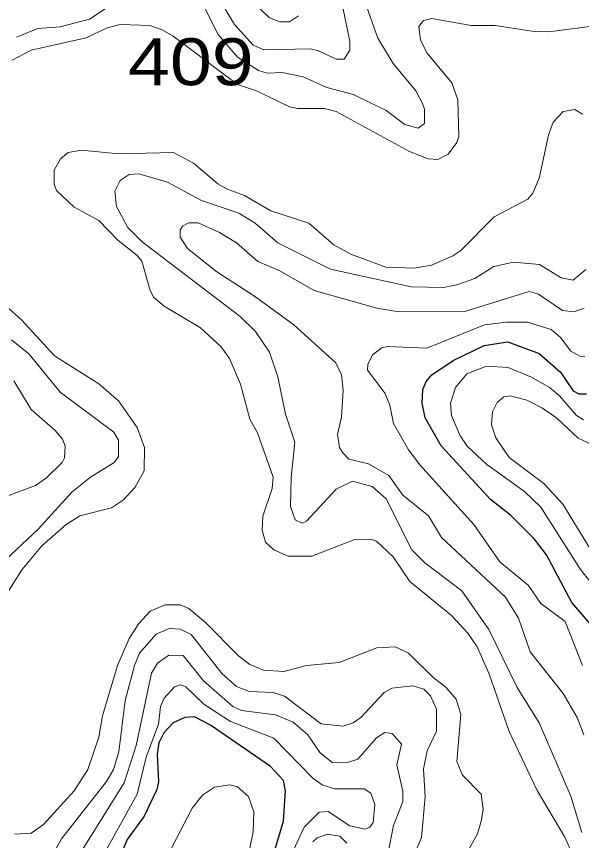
# Model space of a CAD drawing. Extents: x 577 to 602.9, y 7483.8 to 7511.6.
# Drawn here: x 593.033 to 593.996, y 7486.38 to 7487.785 of the extents above; entities that cross this region are included whole.
import ezdxf
from ezdxf.enums import TextEntityAlignment as Align

# ---------------------------------------------------------------- set-up
doc = ezdxf.new("R2010")
doc.units = 0
doc.header["$LTSCALE"] = 0.032
doc.layers.add('1', color=7, linetype='Continuous', lineweight=25)
doc.layers.add('2', color=7, linetype='Continuous', lineweight=13)
doc.layers.add('61', color=7, linetype='Continuous')

msp = doc.modelspace()

# ---------------------------------------------------------------- linework, layer by layer
at = {"layer": '1'}
for points in [[(594.0639, 7486.6885), (593.9796, 7486.7863), (593.9367, 7486.8674), (593.916, 7486.8945), (593.8755, 7486.935), (593.8413, 7486.9621), (593.757, 7487.0535), (593.73, 7487.1012), (593.7244, 7487.1259), (593.726, 7487.1497), (593.7316, 7487.1632), (593.7411, 7487.1744), (593.7777, 7487.199), (593.8302, 7487.2245), (593.8707, 7487.2308), (593.924, 7487.211), (593.9606, 7487.1792), (593.982, 7487.1473), (593.9916, 7487.1418), (594.0051, 7487.1418)], [(593.4715, 7486.3585), (593.4882, 7486.4134), (593.4914, 7486.4651), (593.4882, 7486.4826), (593.466, 7486.5064), (593.3634, 7486.5772), (593.3364, 7486.5915), (593.3197, 7486.5899), (593.2998, 7486.5812), (593.284, 7486.564), (593.2755, 7486.5469), (593.2727, 7486.5279), (593.2751, 7486.4802), (593.2719, 7486.4675), (593.2505, 7486.4221), (593.2218, 7486.3824), (593.1892, 7486.3045)]]:
    msp.add_lwpolyline(points, dxfattribs=at)
at = {"layer": '2'}
for points in [[(593.5137, 7487.7867), (593.4986, 7487.7763), (593.4819, 7487.7763), (593.4641, 7487.783), (593.3906, 7487.8547)], [(593.2163, 7487.8209), (593.1574, 7487.7811)], [(593.375, 7487.8214), (593.4047, 7487.7716), (593.4365, 7487.7366), (593.4548, 7487.7286), (593.5336, 7487.7302), (593.5479, 7487.727), (593.5781, 7487.7127), (593.5916, 7487.7127), (593.6011, 7487.7278), (593.6011, 7487.7429), (593.5852, 7487.8209)], [(593.6266, 7487.8113), (593.6489, 7487.7485), (593.6751, 7487.7056), (593.7141, 7487.6586), (593.7252, 7487.6372), (593.7284, 7487.6276), (593.7284, 7487.603), (593.718, 7487.595), (593.695, 7487.6014), (593.6632, 7487.6252), (593.6075, 7487.6523), (593.5622, 7487.6642), (593.5216, 7487.6825), (593.4858, 7487.6897), (593.4604, 7487.6889), (593.4453, 7487.6936), (593.4095, 7487.7159), (593.3769, 7487.7549), (593.3536, 7487.8006)], [(594.0234, 7487.77), (593.9407, 7487.7596), (593.9121, 7487.7604), (593.8492, 7487.77), (593.8079, 7487.77), (593.7411, 7487.7819), (593.7268, 7487.7787), (593.7188, 7487.7684), (593.722, 7487.7453), (593.7331, 7487.7231), (593.7753, 7487.6722), (593.7856, 7487.6435), (593.7872, 7487.5807), (593.784, 7487.5704), (593.7689, 7487.5505), (593.7514, 7487.5418), (593.7347, 7487.5425), (593.7029, 7487.5553), (593.5781, 7487.6237), (593.5582, 7487.6284), (593.5121, 7487.6284), (593.4986, 7487.6316), (593.4421, 7487.6586), (593.4095, 7487.6698), (593.2998, 7487.7517), (593.2815, 7487.7628), (593.26, 7487.77), (593.2099, 7487.7716), (593.1877, 7487.766), (593.1519, 7487.7493), (593.058, 7487.7278), (593.0254, 7487.7111)], [(593.1574, 7487.7811), (593.1073, 7487.7676), (593.0692, 7487.7652), (593.0326, 7487.7501)], [(593.396, 7487.2022), (593.3817, 7487.2221), (593.3467, 7487.2547), (593.2847, 7487.2913), (593.2672, 7487.3064), (593.2608, 7487.3183), (593.2465, 7487.3684), (593.2385, 7487.3779), (593.2059, 7487.4042), (593.1733, 7487.4376), (593.1312, 7487.4606), (593.101, 7487.4885), (593.097, 7487.4996), (593.097, 7487.5235), (593.1081, 7487.5425), (593.1209, 7487.5537), (593.1439, 7487.5577), (593.2075, 7487.5513), (593.3006, 7487.5537), (593.3348, 7487.5354), (593.3761, 7487.5004), (593.3912, 7487.4917), (593.4214, 7487.4805), (593.4668, 7487.4543), (593.5312, 7487.4328), (593.5741, 7487.3962), (593.6027, 7487.3803), (593.6624, 7487.3581), (593.7109, 7487.3565), (593.7403, 7487.3612), (593.7769, 7487.3772), (593.7904, 7487.3867), (593.8476, 7487.4439), (593.9049, 7487.4742), (593.9136, 7487.4845), (593.924, 7487.5099), (593.9399, 7487.5831), (593.9478, 7487.6054), (593.9653, 7487.6237), (593.9852, 7487.6268), (593.9979, 7487.6189)], [(593.8866, 7486.6416), (593.8381, 7486.7402), (593.792, 7486.8062), (593.7292, 7486.8539), (593.7069, 7486.8762), (593.6632, 7486.9629), (593.6393, 7486.9843), (593.6059, 7486.9931), (593.5781, 7486.9796), (593.5272, 7486.9247), (593.52, 7486.9215), (593.5081, 7486.9271), (593.5002, 7486.9501), (593.501, 7486.9994), (593.5073, 7487.0599), (593.4914, 7487.1076), (593.4787, 7487.1712), (593.4644, 7487.2133), (593.4405, 7487.2483), (593.4143, 7487.2738), (593.2473, 7487.401), (593.2226, 7487.4257), (593.2036, 7487.4614), (593.2004, 7487.4877), (593.2099, 7487.506), (593.225, 7487.5163), (593.2417, 7487.5171), (593.2902, 7487.5028), (593.3483, 7487.4718), (593.4119, 7487.4503), (593.4397, 7487.4328), (593.4787, 7487.3994), (593.5685, 7487.3549), (593.7061, 7487.3247), (593.761, 7487.3231), (593.784, 7487.3278), (593.8143, 7487.339), (593.8469, 7487.3589), (593.8803, 7487.3668), (593.9248, 7487.3628), (593.9614, 7487.3398), (593.982, 7487.3358), (594.0035, 7487.3541)], [(594.0011, 7487.2881), (593.9836, 7487.2817), (593.9637, 7487.2841), (593.9232, 7487.3119), (593.9073, 7487.3167), (593.7991, 7487.2833), (593.6846, 7487.2817), (593.6473, 7487.2881), (593.5407, 7487.3183), (593.4819, 7487.3517), (593.4445, 7487.3676), (593.4079, 7487.3994), (593.3793, 7487.4169), (593.3427, 7487.4336), (593.3268, 7487.4336), (593.3157, 7487.428), (593.3117, 7487.4209), (593.3117, 7487.409), (593.3244, 7487.3899), (593.3745, 7487.3501), (593.4389, 7487.3088), (593.5057, 7487.2595), (593.5773, 7487.1951), (593.5868, 7487.1744), (593.59, 7487.1481), (593.5868, 7487.102), (593.5805, 7487.0726), (593.5837, 7487.0503), (593.5892, 7487.0416), (593.5996, 7487.0305), (593.633, 7487.0225), (593.6679, 7487.0026), (593.6918, 7486.9692), (593.7355, 7486.9342), (593.7578, 7486.8969), (593.8667, 7486.7951), (593.889, 7486.7593), (593.9089, 7486.702), (593.9653, 7486.6313), (593.9892, 7486.5899), (594.0003, 7486.5605)], [(593, 7487.3048), (593.0413, 7487.2682), (593.0978, 7487.207), (593.1733, 7487.1593), (593.2067, 7487.1299), (593.2385, 7487.0845), (593.2513, 7487.0503), (593.2505, 7487.0106), (593.2354, 7486.9827), (593.2155, 7486.9613), (593.1948, 7486.9478), (593.1407, 7486.9342), (593.1177, 7486.9191), (593.0763, 7486.8826), (593.0421, 7486.842), (592.9904, 7486.7609)], [(594.0019, 7487.2054), (593.9932, 7487.2062), (593.9781, 7487.2149), (593.9606, 7487.238), (593.9447, 7487.2515), (593.9041, 7487.2642), (593.8683, 7487.2642), (593.831, 7487.2595), (593.7323, 7487.2197), (593.6656, 7487.2229), (593.656, 7487.2205), (593.6401, 7487.2086), (593.6322, 7487.1919), (593.6314, 7487.1823), (593.6616, 7487.1426), (593.6695, 7487.1227), (593.6759, 7487.0917), (593.7013, 7487.0464), (593.7204, 7487.0209), (593.8127, 7486.9191), (593.8572, 7486.8555), (593.9057, 7486.815), (593.9272, 7486.7847), (593.9685, 7486.7537), (593.9979, 7486.679)], [(593.0246, 7487.234), (593.0541, 7487.2102), (593.1073, 7487.145), (593.1988, 7487.0766), (593.2067, 7487.0631), (593.2067, 7487.0344), (593.1996, 7487.0249), (593.159, 7487.0002), (593.128, 7486.9748), (593.07, 7486.9112), (593.004, 7486.8499)], [(593.9876, 7486.3418), (593.9677, 7486.3864), (593.9208, 7486.4659), (593.8731, 7486.5661), (593.8381, 7486.6655), (593.8182, 7486.7108), (593.8023, 7486.7339), (593.7745, 7486.7641), (593.7037, 7486.8221), (593.6751, 7486.8643), (593.6473, 7486.8905), (593.6369, 7486.8945), (593.6099, 7486.8937), (593.5367, 7486.8651), (593.4962, 7486.8651), (593.4715, 7486.8762), (593.4572, 7486.8889), (593.4517, 7486.9096), (593.4532, 7486.9334), (593.4691, 7486.9804), (593.4707, 7487.0002), (593.4437, 7487.0758), (593.431, 7487.0988), (593.4151, 7487.1585), (593.396, 7487.2022)], [(594.0695, 7486.749), (593.9948, 7486.8428), (593.9272, 7486.9486), (593.8993, 7486.9756), (593.8349, 7487.0217), (593.8015, 7487.0527), (593.7896, 7487.0702), (593.7745, 7487.1052), (593.7729, 7487.1259), (593.7817, 7487.1529), (593.8007, 7487.176), (593.8341, 7487.1895), (593.8715, 7487.1871), (593.9113, 7487.1704), (593.9415, 7487.1529), (593.959, 7487.1386), (593.9876, 7487.1052), (593.9995, 7487.098)], [(593.0064, 7486.9637), (593.0652, 7486.9859), (593.0843, 7486.9986), (593.1105, 7487.0249), (593.1145, 7487.0328), (593.1161, 7487.0527), (593.1113, 7487.0646), (593.0986, 7487.0798), (593.058, 7487.1155), (593.0286, 7487.164)], [(594.0409, 7486.8293), (593.9645, 7486.9541), (593.9319, 7486.9891), (593.8731, 7487.0336), (593.85, 7487.067), (593.8429, 7487.0893), (593.8445, 7487.1116), (593.8524, 7487.1275), (593.8636, 7487.137), (593.8755, 7487.1386), (593.9033, 7487.1314), (593.9296, 7487.1179), (593.9542, 7487.1004), (593.9908, 7487.0662), (594.0138, 7487.0559)], [(593.0294, 7486.3911), (593.058, 7486.3927), (593.0787, 7486.4078), (593.1312, 7486.4651), (593.1543, 7486.5017), (593.1733, 7486.5565), (593.1797, 7486.5931), (593.2051, 7486.679), (593.225, 7486.7251), (593.2417, 7486.7506), (593.2608, 7486.7712), (593.2863, 7486.7824), (593.3117, 7486.7824), (593.3268, 7486.776), (593.3554, 7486.7521), (593.4119, 7486.6949), (593.431, 7486.6806), (593.454, 7486.671), (593.489, 7486.6686), (593.5272, 7486.679), (593.5829, 7486.6838), (593.6473, 7486.7092), (593.6791, 7486.7108), (593.7013, 7486.6997), (593.7427, 7486.6591), (593.7657, 7486.6416), (593.7824, 7486.6217), (593.7904, 7486.5955), (593.784, 7486.5152), (593.7936, 7486.4921), (593.8254, 7486.4595), (593.8286, 7486.4333), (593.8254, 7486.4134), (593.819, 7486.3919), (593.8031, 7486.3633)], [(593.0898, 7486.3474), (593.1097, 7486.3832), (593.1861, 7486.481), (593.198, 7486.5017), (593.2075, 7486.5319), (593.2179, 7486.6193), (593.2338, 7486.679), (593.2425, 7486.6997), (593.2711, 7486.7323), (593.2934, 7486.7418), (593.3117, 7486.741), (593.3308, 7486.7315), (593.3833, 7486.6647), (593.4079, 7486.6432), (593.4302, 7486.6345), (593.4707, 7486.6329), (593.4898, 7486.6265), (593.5526, 7486.5796), (593.5892, 7486.5756), (593.6067, 7486.5812), (593.6202, 7486.5899), (593.66, 7486.6329), (593.6727, 7486.64), (593.7085, 7486.644), (593.7276, 7486.6384), (593.7387, 7486.6273), (593.749, 7486.6042), (593.749, 7486.5669), (593.7331, 7486.5335), (593.7268, 7486.5025), (593.73, 7486.4547), (593.7236, 7486.3856), (593.6918, 7486.31)], [(593.6663, 7486.3569), (593.6759, 7486.4062), (593.6918, 7486.4468), (593.6918, 7486.4643), (593.6815, 7486.5096), (593.6894, 7486.5446), (593.6735, 7486.5629), (593.6608, 7486.5645), (593.6465, 7486.5557), (593.6147, 7486.5192), (593.5956, 7486.5128), (593.5709, 7486.5136), (593.5503, 7486.5303), (593.5296, 7486.5605), (593.5049, 7486.582), (593.4747, 7486.5947), (593.4167, 7486.6019), (593.4016, 7486.609), (593.3515, 7486.6527), (593.3173, 7486.6957), (593.2926, 7486.6965), (593.2735, 7486.683), (593.2632, 7486.6655), (593.237, 7486.5422), (593.2163, 7486.4786), (593.1447, 7486.3641)], [(593.4691, 7486.2854), (593.5232, 7486.4031), (593.5487, 7486.4285), (593.5646, 7486.4301), (593.6011, 7486.4054), (593.6274, 7486.3999), (593.6353, 7486.4031), (593.6409, 7486.411), (593.6441, 7486.442), (593.6369, 7486.4611), (593.6258, 7486.4683), (593.5749, 7486.4683), (593.5542, 7486.4754), (593.5383, 7486.4866), (593.4715, 7486.5549), (593.3976, 7486.5836), (593.3523, 7486.613), (593.3212, 7486.6432), (593.3125, 7486.6456), (593.3022, 7486.6424), (593.2847, 7486.6233), (593.2783, 7486.609), (593.2751, 7486.5788)], [(593.9971, 7486.3943), (593.9781, 7486.4563), (593.924, 7486.5812), (593.8866, 7486.6416)], [(593.2751, 7486.5788), (593.2539, 7486.5227), (593.2385, 7486.4595), (593.1861, 7486.3649)], [(593.5383, 7486.3784), (593.5455, 7486.3848), (593.563, 7486.3911), (593.5844, 7486.388), (593.5964, 7486.376)]]:
    msp.add_lwpolyline(points, dxfattribs=at)
msp.add_lwpolyline([(593.2616, 7486.2981), (593.3324, 7486.4357), (593.3499, 7486.4579), (593.3705, 7486.4714), (593.3968, 7486.4754), (593.4095, 7486.4722), (593.4286, 7486.4555), (593.4373, 7486.4293), (593.4365, 7486.3951), (593.431, 7486.3673), (593.3984, 7486.2933), (593.3451, 7486.1963), (593.3157, 7486.112), (593.2966, 7486.077), (593.2878, 7486.0707), (593.2767, 7486.0723), (593.2632, 7486.0929), (593.26, 7486.1184), (593.2616, 7486.1422), (593.2529, 7486.2051), (593.2563, 7486.2674)], close=True, dxfattribs=at)

# ---------------------------------------------------------------- texts
at = {"layer": '61', "width": 1.2}
msp.add_text('409', height=0.08, dxfattribs=at).set_placement((593.3302, 7487.6683), align=Align.CENTER)

doc.saveas('drawing.dxf')
